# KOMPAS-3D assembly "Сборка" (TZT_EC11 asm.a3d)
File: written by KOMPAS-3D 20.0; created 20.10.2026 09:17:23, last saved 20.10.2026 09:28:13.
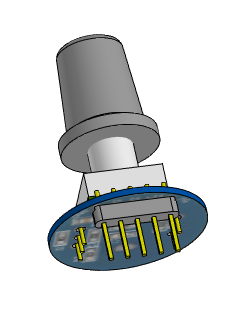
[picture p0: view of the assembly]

Document properties: Полное имя файла: D:\myProjects\Progect_esp32\box_compas\переключатели и кнопки\TZT_EC11 asm.a3d

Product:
- Part/product: Сборка
    Масса: 0.0191475
  - Component [detail]: Деталь  | Масса: 0.000635679; source file: ..\разъемы\pls_5.m3d
  - Component [detail]: Деталь  | Материал: Фторопласт-4  ГОСТ 10007-80 Е (density 2200 kg/m3); Масса: 0.00354823; source file: EC11 S.m3d
  - Component [detail]: Деталь  | Материал: Фторопласт-4  ГОСТ 10007-80 Е (density 2200 kg/m3); Масса: 0.000956379; source file: TZT_EC11 pcb.m3d.bak
  - Component [detail]: Деталь  | Масса: 0.0140072; source file: ..\ручки\ручка.m3d

Referenced files in D:\myProjects\Progect_esp32\box_compas\переключатели и кнопки\: TZT_EC11 pcb.m3d.bak, EC11 S.m3d
Referenced files in D:\myProjects\Progect_esp32\box_compas\разъемы\: pls_5.m3d
Referenced files in D:\myProjects\Progect_esp32\box_compas\ручки\: ручка.m3d
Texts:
  TZT_EC11 pcb.m3d.bak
